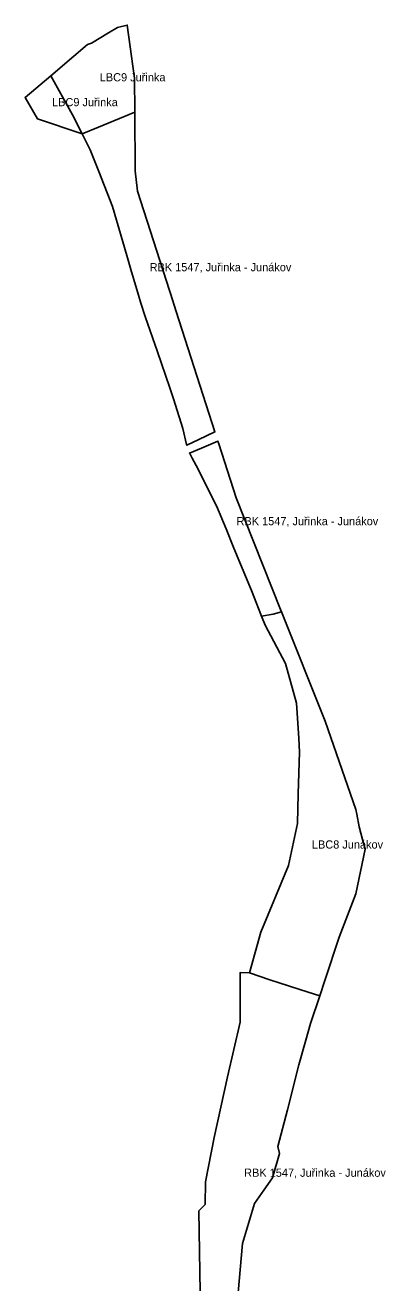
# Model space of a CAD drawing. Extents: x -502026 to -497556, y -1143322 to -1138019.
# Drawn here: x -498051 to -497698, y -1139249 to -1138019 of the extents above; entities that cross this region are included whole.
import ezdxf

# ---------------------------------------------------------------- set-up
doc = ezdxf.new("R2010")
doc.units = 0
for name, color, linetype in [('13', 7, 'Continuous'), ('16', 7, 'Continuous'), ('17', 7, 'Continuous')]:
    doc.layers.add(name, color=color, linetype=linetype)

msp = doc.modelspace()

# ---------------------------------------------------------------- linework, layer by layer
at = {"layer": '13'}
for points in [[(-497881.278, -1138424.655), (-497892.94, -1138430.17), (-497893.17, -1138429.5), (-497896.78, -1138413.6), (-497906.02, -1138384.62), (-497909.68, -1138373.88), (-497921.61, -1138338.83), (-497933.63, -1138304.29), (-497937.91, -1138291.03), (-497940.22, -1138283.23), (-497947.61, -1138258.35), (-497951.68, -1138244.57), (-497965.73, -1138196.49), (-497979.08, -1138162.54), (-497987.36, -1138141.13), (-497995.22, -1138125.715), (-497979.401, -1138119.122), (-497943.81, -1138104.29), (-497943.4, -1138161.69), (-497941.29, -1138181.62), (-497909.97, -1138278.82), (-497909.05, -1138281.67), (-497903.34, -1138299.38), (-497865.39, -1138417.14)], [(-497800.232, -1138593.067), (-497808.436, -1138595.28), (-497819.789, -1138597.413), (-497829.67, -1138572.21), (-497846.87, -1138530.92), (-497854.54, -1138512), (-497863.77, -1138489.23), (-497883.82, -1138449.97), (-497887.82, -1138442.61), (-497890.13, -1138438.35), (-497890.32, -1138437.79), (-497878.666, -1138432.944), (-497862.47, -1138426.21), (-497861.66, -1138428.73), (-497844.68, -1138481.4), (-497801.21, -1138590.61)]]:
    msp.add_lwpolyline(points, close=True, dxfattribs=at)
msp.add_lwpolyline([(-497880.04, -1139258.3), (-497881.28, -1139178.83), (-497875.07, -1139172.63), (-497874.52, -1139150.43), (-497866.12, -1139107.13), (-497853.02, -1139047.85), (-497840.85, -1138994.18), (-497840.85, -1138991.11), (-497840.9, -1138945.87), (-497831.57, -1138946.17), (-497811.631, -1138952.872), (-497774.269, -1138965.051), (-497763.058, -1138968.705), (-497772.19, -1138995.73), (-497776.61, -1139011.77), (-497783.33, -1139036.08), (-497794.56, -1139080.14), (-497803.89, -1139115.86), (-497802.28, -1139122.88), (-497809.15, -1139146.42), (-497817.58, -1139158.44), (-497826.73, -1139171.48), (-497838.59, -1139210.88), (-497846.62, -1139303.16)], dxfattribs=at)
at = {"layer": '16'}
for points in [[(-497979.401, -1138119.122), (-497995.22, -1138125.715), (-498004.81, -1138106.91), (-498025.92, -1138068.99), (-498003.46, -1138049.73), (-497990.17, -1138038.33), (-497986.07, -1138036.87), (-497969.54, -1138026.9), (-497960.73, -1138021.59), (-497951.09, -1138019.31), (-497944.04, -1138071.14), (-497943.81, -1138104.29)], [(-497757.95, -1138953.59), (-497763.058, -1138968.705), (-497774.269, -1138965.051), (-497811.631, -1138952.872), (-497831.57, -1138946.17), (-497820.44, -1138906.33), (-497793.61, -1138841), (-497784.86, -1138800.07), (-497784.12, -1138771.02), (-497782.74, -1138730.21), (-497783.56, -1138716.62), (-497785.87, -1138682.33), (-497796.52, -1138643.47), (-497816.43, -1138605.98), (-497819.789, -1138597.413), (-497808.436, -1138595.28), (-497800.232, -1138593.067), (-497757.73, -1138699.81), (-497730.19, -1138778.85), (-497727.6, -1138786.3), (-497726.76, -1138791), (-497724.59, -1138803.21), (-497721.27, -1138815.8), (-497718.61, -1138825.06), (-497727.86, -1138868.87), (-497744.11, -1138911.12)]]:
    msp.add_lwpolyline(points, close=True, dxfattribs=at)
at = {"layer": '17'}
msp.add_lwpolyline([(-497995.22, -1138125.715), (-498039.01, -1138110.81), (-498050.965, -1138090.021), (-498025.92, -1138068.99), (-498004.81, -1138106.91)], close=True, dxfattribs=at)

# ---------------------------------------------------------------- texts
at = {"layer": '13'}
for p in [(-497929.289, -1138259.991), (-497844.337, -1138508.348), (-497836.9, -1139145.521)]:
    msp.add_text('RBK 1547, Juřinka - Junákov', height=8, dxfattribs=at).set_placement(p)
at = {"layer": '16'}
for s, p in [('LBC9 Juřinka', (-497978.037, -1138074.272)), ('LBC8 Junákov', (-497770.652, -1138824.549))]:
    msp.add_text(s, height=8, dxfattribs=at).set_placement(p)
at = {"layer": '17'}
msp.add_text('LBC9 Juřinka', height=8, dxfattribs=at).set_placement((-498024.658, -1138098.575))

doc.saveas('drawing.dxf')
